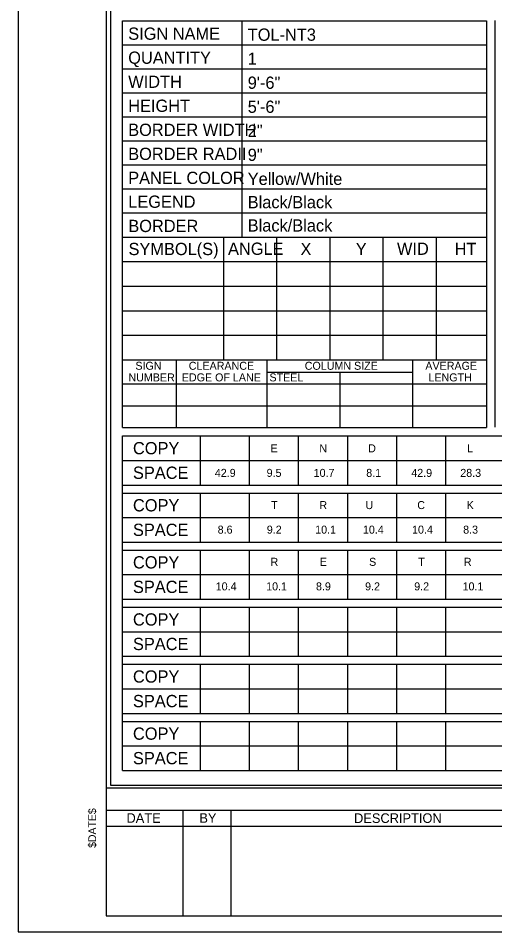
# Model space of a CAD drawing. Extents: x 17890628 to 17890844, y 17897506 to 17897992.
# Drawn here: x 17890700.47 to 17890726.43, y 17897507.81 to 17897557.55 of the extents above; entities that cross this region are included whole.
import ezdxf

# ---------------------------------------------------------------- set-up
doc = ezdxf.new("R2010")
doc.units = 0
for name, color, linetype in [('GSSign', 7, 'Continuous'), ('PlotBorder_dp', 7, 'Continuous'), ('SheetBorder_dp', 7, 'Continuous'), ('SheetLines_dp', 7, 'Continuous'), ('SheetLinesMisc2_dp', 7, 'Continuous'), ('TextMinor', 7, 'Continuous'), ('TextMisc', 7, 'Continuous')]:
    doc.layers.add(name, color=color, linetype=linetype)

msp = doc.modelspace()

# ---------------------------------------------------------------- linework, layer by layer
at = {"layer": 'PlotBorder_dp'}
msp.add_lwpolyline([(17890700.471, 17897507.81), (17890844.155, 17897507.81), (17890844.155, 17897600.116), (17890700.471, 17897600.116)], close=True, dxfattribs=at)
at = {"layer": 'SheetBorder_dp'}
for p, q in [((17890705.26, 17897599.245), (17890705.26, 17897508.681)), ((17890705.26, 17897515.647), (17890839.365, 17897515.647)), ((17890705.26, 17897508.681), (17890839.365, 17897508.681))]:
    msp.add_line(p, q, dxfattribs=at)
at = {"layer": 'SheetLines_dp'}
for p, q in [((17890705.26, 17897514.428), (17890755.419, 17897514.428)), ((17890709.44, 17897514.428), (17890709.44, 17897508.681)), ((17890712.052, 17897514.428), (17890712.052, 17897508.681)), ((17890705.26, 17897513.557), (17890755.419, 17897513.557))]:
    msp.add_line(p, q, dxfattribs=at)
at = {"layer": 'SheetLinesMisc2_dp'}
for p, q in [((17890705.5, 17897599.039), (17890705.5, 17897515.791)), ((17890706.142, 17897535.259), (17890706.142, 17897557.415)), ((17890706.142, 17897557.415), (17890725.973, 17897557.415)), ((17890712.643, 17897557.415), (17890712.643, 17897556.106)), ((17890725.973, 17897557.415), (17890725.973, 17897535.259)), ((17890726.429, 17897557.416), (17890726.429, 17897535.291)), ((17890706.142, 17897556.106), (17890725.973, 17897556.106)), ((17890712.643, 17897556.106), (17890712.643, 17897545.634)), ((17890706.142, 17897554.797), (17890725.973, 17897554.797)), ((17890706.142, 17897553.489), (17890725.973, 17897553.489)), ((17890706.142, 17897552.18), (17890725.973, 17897552.18)), ((17890706.142, 17897550.871), (17890725.973, 17897550.871)), ((17890706.142, 17897549.563), (17890725.973, 17897549.563)), ((17890706.142, 17897548.254), (17890716.057, 17897548.254)), ((17890716.057, 17897548.254), (17890725.973, 17897548.254)), ((17890706.142, 17897546.946), (17890716.057, 17897546.946)), ((17890716.057, 17897546.946), (17890725.973, 17897546.946)), ((17890706.141, 17897545.634), (17890725.973, 17897545.634)), ((17890711.644, 17897545.634), (17890711.644, 17897538.953)), ((17890714.542, 17897545.634), (17890714.542, 17897538.953)), ((17890717.44, 17897545.634), (17890717.44, 17897538.953)), ((17890720.337, 17897545.634), (17890720.337, 17897538.953)), ((17890723.235, 17897545.634), (17890723.235, 17897538.953)), ((17890706.141, 17897544.298), (17890725.973, 17897544.298)), ((17890706.141, 17897542.961), (17890725.973, 17897542.961)), ((17890706.141, 17897541.625), (17890725.973, 17897541.625)), ((17890706.141, 17897540.289), (17890725.973, 17897540.289)), ((17890706.141, 17897538.953), (17890725.973, 17897538.953)), ((17890709.08, 17897538.953), (17890709.08, 17897535.26)), ((17890714.015, 17897538.953), (17890714.015, 17897535.26)), ((17890721.947, 17897538.953), (17890721.947, 17897535.26)), ((17890714.015, 17897538.272), (17890721.947, 17897538.272)), ((17890717.981, 17897538.272), (17890717.981, 17897535.26)), ((17890706.141, 17897537.633), (17890725.973, 17897537.633)), ((17890706.141, 17897536.446), (17890725.973, 17897536.446)), ((17890706.142, 17897535.259), (17890725.973, 17897535.259)), ((17890706.142, 17897534.804), (17890771.912, 17897534.804)), ((17890706.142, 17897516.593), (17890706.142, 17897534.804)), ((17890710.375, 17897534.804), (17890710.375, 17897532.131)), ((17890713.051, 17897534.804), (17890713.051, 17897532.131)), ((17890715.727, 17897534.804), (17890715.727, 17897532.131)), ((17890718.402, 17897534.804), (17890718.402, 17897532.131)), ((17890721.077, 17897534.804), (17890721.077, 17897532.131)), ((17890723.753, 17897534.804), (17890723.753, 17897532.131)), ((17890706.142, 17897533.468), (17890771.912, 17897533.468)), ((17890706.142, 17897532.131), (17890771.912, 17897532.131)), ((17890706.142, 17897531.696), (17890771.912, 17897531.696)), ((17890710.375, 17897531.696), (17890710.375, 17897529.023)), ((17890713.051, 17897531.696), (17890713.051, 17897529.023)), ((17890715.727, 17897531.696), (17890715.727, 17897529.023)), ((17890718.402, 17897531.696), (17890718.402, 17897529.023)), ((17890721.077, 17897531.696), (17890721.077, 17897529.023)), ((17890723.753, 17897531.696), (17890723.753, 17897529.023)), ((17890706.142, 17897530.359), (17890771.912, 17897530.359)), ((17890706.142, 17897529.023), (17890771.912, 17897529.023)), ((17890706.142, 17897528.588), (17890771.912, 17897528.588)), ((17890710.375, 17897528.588), (17890710.375, 17897525.916)), ((17890713.051, 17897528.588), (17890713.051, 17897525.916)), ((17890715.727, 17897528.588), (17890715.727, 17897525.916)), ((17890718.402, 17897528.588), (17890718.402, 17897525.916)), ((17890721.077, 17897528.588), (17890721.077, 17897525.916)), ((17890723.753, 17897528.588), (17890723.753, 17897525.916)), ((17890706.142, 17897527.252), (17890771.912, 17897527.252)), ((17890706.142, 17897525.916), (17890771.912, 17897525.916)), ((17890706.142, 17897525.48), (17890771.912, 17897525.48)), ((17890710.375, 17897525.48), (17890710.375, 17897522.808)), ((17890713.051, 17897525.48), (17890713.051, 17897522.808)), ((17890715.727, 17897525.48), (17890715.727, 17897522.808)), ((17890718.402, 17897525.48), (17890718.402, 17897522.808)), ((17890721.077, 17897525.48), (17890721.077, 17897522.808)), ((17890723.753, 17897525.48), (17890723.753, 17897522.808)), ((17890706.142, 17897524.145), (17890771.912, 17897524.145)), ((17890706.142, 17897522.808), (17890771.912, 17897522.808)), ((17890706.142, 17897522.372), (17890771.912, 17897522.372)), ((17890710.375, 17897522.372), (17890710.375, 17897519.7)), ((17890713.051, 17897522.372), (17890713.051, 17897519.7)), ((17890715.727, 17897522.372), (17890715.727, 17897519.7)), ((17890718.402, 17897522.372), (17890718.402, 17897519.7)), ((17890721.077, 17897522.372), (17890721.077, 17897519.7)), ((17890723.753, 17897522.372), (17890723.753, 17897519.7)), ((17890706.142, 17897521.036), (17890771.912, 17897521.036)), ((17890706.142, 17897519.7), (17890771.912, 17897519.7)), ((17890706.142, 17897519.264), (17890771.912, 17897519.264)), ((17890710.375, 17897519.264), (17890710.375, 17897516.593)), ((17890713.051, 17897519.264), (17890713.051, 17897516.593)), ((17890715.727, 17897519.264), (17890715.727, 17897516.593)), ((17890718.402, 17897519.264), (17890718.402, 17897516.593)), ((17890721.077, 17897519.264), (17890721.077, 17897516.593)), ((17890723.753, 17897519.264), (17890723.753, 17897516.593)), ((17890706.142, 17897517.928), (17890771.912, 17897517.928)), ((17890706.142, 17897516.593), (17890771.912, 17897516.593)), ((17890705.5, 17897515.791), (17890839.233, 17897515.791))]:
    msp.add_line(p, q, dxfattribs=at)

# ---------------------------------------------------------------- texts
at = {"layer": 'GSSign'}
for s, height, p in [('TOL-NT3', 0.6667, (17890712.971, 17897556.321)), ('1', 0.667, (17890712.971, 17897555.013)), ('9\'-6"', 0.6667, (17890712.971, 17897553.704)), ('5\'-6"', 0.6667, (17890712.971, 17897552.396)), ('2"', 0.6667, (17890712.971, 17897551.087)), ('9"', 0.6667, (17890712.971, 17897549.778)), ('Yellow/White', 0.66667, (17890712.971, 17897548.47)), ('Black/Black', 0.66667, (17890712.971, 17897547.201)), ('Black/Black', 0.66667, (17890712.971, 17897545.932)), ('E', 0.436, (17890714.215, 17897533.911)), ('N', 0.436, (17890716.873, 17897533.911)), ('D', 0.436, (17890719.534, 17897533.911)), ('L', 0.436, (17890724.93, 17897533.911)), ('42.9', 0.4357, (17890711.18, 17897532.575)), ('9.5', 0.4357, (17890714.002, 17897532.575)), ('10.7', 0.4357, (17890716.564, 17897532.575)), ('8.1', 0.4357, (17890719.429, 17897532.575)), ('42.9', 0.4357, (17890721.882, 17897532.575)), ('28.3', 0.4357, (17890724.552, 17897532.575)), ('T', 0.436, (17890714.25, 17897530.822)), ('R', 0.436, (17890716.875, 17897530.822)), ('U', 0.436, (17890719.386, 17897530.822)), ('C', 0.436, (17890722.209, 17897530.822)), ('K', 0.436, (17890724.899, 17897530.822)), ('8.6', 0.4357, (17890711.334, 17897529.485)), ('9.2', 0.4357, (17890714.012, 17897529.485)), ('10.1', 0.4357, (17890716.647, 17897529.485)), ('10.4', 0.4357, (17890719.249, 17897529.485)), ('10.4', 0.4357, (17890721.924, 17897529.485)), ('8.3', 0.4357, (17890724.708, 17897529.485)), ('R', 0.436, (17890714.212, 17897527.732)), ('E', 0.436, (17890716.898, 17897527.732)), ('S', 0.436, (17890719.584, 17897527.732)), ('T', 0.436, (17890722.26, 17897527.732)), ('R', 0.436, (17890724.745, 17897527.732)), ('10.4', 0.4357, (17890711.228, 17897526.396)), ('10.1', 0.4357, (17890713.975, 17897526.396)), ('8.9', 0.4357, (17890716.691, 17897526.396)), ('9.2', 0.4357, (17890719.366, 17897526.396)), ('9.2', 0.4357, (17890722.042, 17897526.396)), ('10.1', 0.4357, (17890724.677, 17897526.396))]:
    msp.add_text(s, height=height, dxfattribs=at).set_placement(p)
at = {"layer": 'TextMinor'}
for s, height, p in [('SIGN NAME', 0.6667, (17890706.461, 17897556.375)), ('QUANTITY', 0.6667, (17890706.461, 17897555.066)), ('WIDTH', 0.6667, (17890706.461, 17897553.757)), ('HEIGHT', 0.6667, (17890706.461, 17897552.449)), ('BORDER WIDTH', 0.66667, (17890706.461, 17897551.14)), ('BORDER RADII', 0.66667, (17890706.461, 17897549.831)), ('PANEL COLOR', 0.66667, (17890706.461, 17897548.523)), ('LEGEND', 0.6667, (17890706.461, 17897547.226)), ('BORDER', 0.6667, (17890706.467, 17897545.906)), ('SYMBOL(S)', 0.6667, (17890706.478, 17897544.651)), ('ANGLE', 0.6667, (17890711.899, 17897544.665)), ('X', 0.667, (17890715.846, 17897544.651)), ('Y', 0.667, (17890718.859, 17897544.651)), ('WID', 0.6667, (17890721.103, 17897544.665)), ('HT', 0.6667, (17890724.244, 17897544.653)), ('SIGN', 0.4357, (17890706.852, 17897538.408)), ('CLEARANCE', 0.4357, (17890709.759, 17897538.407)), ('COLUMN SIZE', 0.43573, (17890716.077, 17897538.407)), ('AVERAGE', 0.4357, (17890722.648, 17897538.407)), ('NUMBER', 0.4357, (17890706.473, 17897537.774)), ('EDGE OF LANE', 0.43573, (17890709.38, 17897537.774)), ('STEEL    ', 0.4357, (17890714.156, 17897537.774)), ('LENGTH', 0.4357, (17890722.817, 17897537.774)), ('COPY', 0.6667, (17890706.719, 17897533.805)), ('SPACE', 0.6667, (17890706.719, 17897532.468)), ('COPY', 0.6667, (17890706.719, 17897530.696)), ('SPACE', 0.6667, (17890706.719, 17897529.36)), ('COPY', 0.6667, (17890706.719, 17897527.589)), ('SPACE', 0.6667, (17890706.719, 17897526.253)), ('COPY', 0.6667, (17890706.719, 17897524.48)), ('SPACE', 0.6667, (17890706.719, 17897523.145)), ('COPY', 0.6667, (17890706.719, 17897521.372)), ('SPACE', 0.6667, (17890706.719, 17897520.036)), ('COPY', 0.6667, (17890706.719, 17897518.264)), ('SPACE', 0.6667, (17890706.719, 17897516.929))]:
    msp.add_text(s, height=height, dxfattribs=at).set_placement(p)
msp.add_text('$DATE$', height=0.4267, rotation=90, dxfattribs=at).set_placement((17890704.711, 17897512.374))
at = {"layer": 'TextMisc'}
for s, height, rotation, p in [('DATE', 0.5225, 359.8693, (17890706.366, 17897513.74)), ('DESCRIPTION', 0.52238, 0.0498, (17890718.766, 17897513.731))]:
    msp.add_text(s, height=height, rotation=rotation, dxfattribs=at).set_placement(p)
msp.add_text('BY', height=0.5225, dxfattribs=at).set_placement((17890710.337, 17897513.74))

doc.saveas('drawing.dxf')
